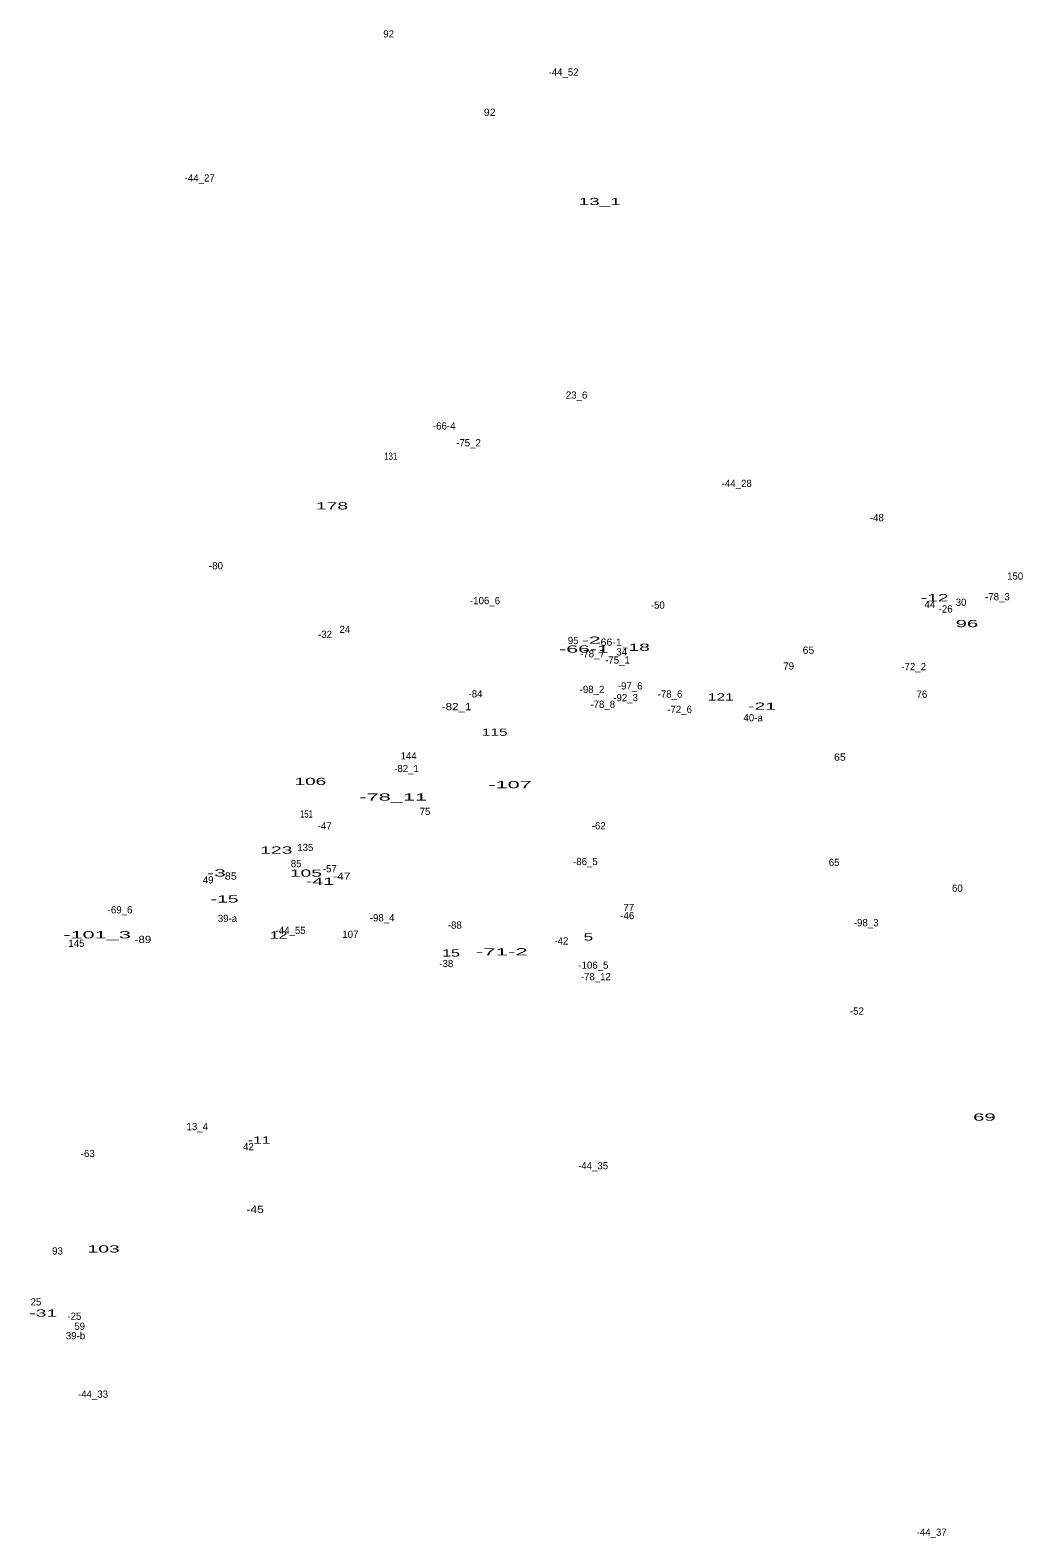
# Model space of a CAD drawing. Extents: x -665231 to -661652, y -987317 to -984562.
# Drawn here: x -663438 to -662888, y -986324 to -985489 of the extents above; entities that cross this region are included whole.
import ezdxf
from ezdxf.enums import TextEntityAlignment as Align

# ---------------------------------------------------------------- set-up
doc = ezdxf.new("R2010")
doc.units = 0
doc.header["$LTSCALE"] = 1.6
doc.layers.add('24', color=7, linetype='Continuous', lineweight=25)

msp = doc.modelspace()

# ---------------------------------------------------------------- texts
at = {"layer": '24'}
for s, p in [('92', (-663239.037, -985492.909)), ('-44_52', (-663142.178, -985514.078)), ('-44_27', (-663343.656, -985572.671)), ('23_6', (-663134.964, -985692.93)), ('-66-4', (-663208.253, -985710.011)), ('-75_2', (-663194.823, -985719.338)), ('-44_28', (-663046.292, -985741.859)), ('-48', (-662968.714, -985760.796)), ('-80', (-663334.651, -985787.413)), ('150', (-662892.107, -985793.172)), ('-78_3', (-662901.933, -985804.611)), ('-106_6', (-663185.665, -985806.736)), ('-50', (-663090.006, -985809.255)), ('44', (-662939.357, -985808.9)), ('-26', (-662930.589, -985811.35)), ('30', (-662922.075, -985807.673)), ('-32', (-663274.264, -985825.442)), ('24', (-663263.303, -985822.669)), ('95', (-663136.855, -985828.85)), ('-78_7', (-663126.176, -985836.195)), ('34', (-663109.961, -985835.157)), ('-75_1', (-663112.337, -985839.651)), ('79', (-663017.528, -985842.972)), ('-72_2', (-662948.299, -985843.286)), ('-97_6', (-663105.289, -985853.985)), ('-84', (-663190.935, -985858.373)), ('-98_2', (-663126.434, -985855.918)), ('-78_8', (-663120.48, -985864.167)), ('-92_3', (-663107.823, -985860.482)), ('-78_6', (-663083.238, -985858.477)), ('76', (-662943.736, -985858.594)), ('-72_6', (-663077.914, -985866.978)), ('40-a', (-663037.227, -985871.624)), ('144', (-663227.98, -985892.74)), ('-82_1', (-663229.137, -985899.754)), ('75', (-663218.911, -985923.503)), ('-47', (-663274.459, -985931.513)), ('-62', (-663122.717, -985931.43)), ('135', (-663285.199, -985943.46)), ('85', (-663290.244, -985952.377)), ('-57', (-663271.595, -985955.213)), ('-86_5', (-663130.104, -985951.23)), ('65', (-662992.329, -985951.757)), ('49', (-663339.015, -985961.418)), ('60', (-662924.105, -985966.042)), ('-69_6', (-663387.779, -985977.972)), ('77', (-663106.088, -985976.723)), ('39-a', (-663328.296, -985982.748)), ('-44_55', (-663293.332, -985989.373)), ('-98_4', (-663242.642, -985982.387)), ('-88', (-663202.421, -985986.454)), ('-46', (-663106.904, -985981.173)), ('-98_3', (-662974.585, -985985.078)), ('145', (-663411.929, -985996.55)), ('107', (-663260.248, -985991.544)), ('-42', (-663143.379, -985995.227)), ('-38', (-663207.136, -986007.734)), ('-106_5', (-663125.653, -986008.638)), ('-78_12', (-663124.342, -986014.98)), ('-52', (-662979.727, -986034.04)), ('13_4', (-663345.004, -986098.037)), ('-63', (-663405.682, -986112.937)), ('42', (-663316.683, -986109.141)), ('-44_35', (-663125.811, -986119.713)), ('93', (-663422.412, -986166.902)), ('25', (-663434.352, -986195.119)), ('-25', (-663413.059, -986203.056)), ('39-b', (-663412.445, -986213.865)), ('59', (-663410.135, -986208.647)), ('-44_33', (-663402.753, -986246.217)), ('-44_37', (-662938.326, -986322.638))]:
    msp.add_text(s, height=4, dxfattribs=at).set_placement(p, align=Align.CENTER)
for s, width, p in [('92', 1.1, (-663183.074, -985536.32)), ('13_1', 1.95, (-663122.202, -985585.719)), ('131', 0.8, (-663237.858, -985726.787)), ('178', 2, (-663270.45, -985754.287)), ('-12', 2, (-662936.662, -985805.157)), ('96', 2.1, (-662918.822, -985819.487)), ('-2', 2.2, (-663126.874, -985828.666)), ('-66-1', 1.1, (-663116.807, -985829.775)), ('-66-1', 2.2, (-663130.854, -985833.565)), ('-18', 2, (-663102.123, -985832.595)), ('65', 1.1, (-663006.581, -985834.193)), ('121', 1.6, (-663055.13, -985860.108)), ('-82_1', 1.2, (-663201.397, -985865.457)), ('-21', 2, (-663032.265, -985865.204)), ('115', 1.6, (-663180.292, -985879.609)), ('65', 1.1, (-662989.152, -985893.406)), ('106', 1.95, (-663282.381, -985906.875)), ('-107', 2.25, (-663171.819, -985908.659)), ('-78_11', 2.25, (-663236.491, -985915.523)), ('151', 0.8, (-663284.57, -985924.92)), ('123', 2, (-663301.234, -985944.909)), ('-3', 2.2, (-663334.404, -985957.574)), ('85', 1.1, (-663326.429, -985959.27)), ('105', 2, (-663284.86, -985957.672)), ('-41', 2.05, (-663277.076, -985962.179)), ('-47', 1.25, (-663264.986, -985959.376)), ('-15', 2, (-663329.902, -985971.981)), ('-101_3', 2.25, (-663400.498, -985991.806)), ('-89', 1.2, (-663375.122, -985994.398)), ('12', 1.65, (-663299.96, -985991.982)), ('5', 1.8, (-663128.431, -985993.012)), ('15', 1.65, (-663204.483, -986001.902)), ('-71-2', 2.3, (-663176.414, -986001.266)), ('69', 2.1, (-662909.144, -986092.782)), ('-11', 1.6, (-663310.767, -986105.494)), ('-45', 1.25, (-663313.031, -986143.891)), ('103', 2, (-663396.851, -986165.777)), ('-31', 2, (-663430.299, -986201.297))]:
    msp.add_text(s, height=4, dxfattribs=dict(at, width=width)).set_placement(p, align=Align.CENTER)

doc.saveas('drawing.dxf')
